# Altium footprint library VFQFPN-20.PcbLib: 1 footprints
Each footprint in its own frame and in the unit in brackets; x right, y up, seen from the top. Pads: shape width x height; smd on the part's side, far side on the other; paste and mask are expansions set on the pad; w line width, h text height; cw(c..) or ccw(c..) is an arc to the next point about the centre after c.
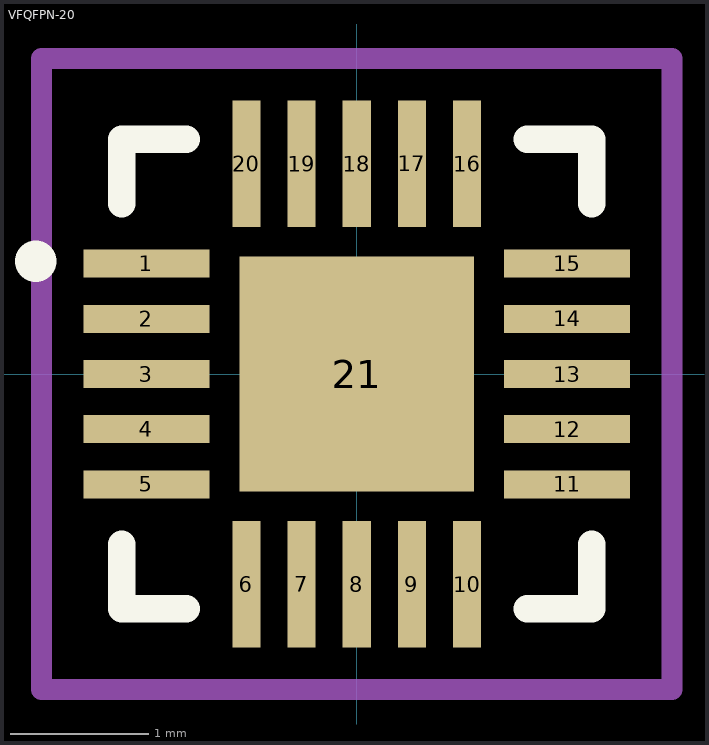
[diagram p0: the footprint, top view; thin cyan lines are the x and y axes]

## VFQFPN-20 [mil]
pads (21):
  rect 36x8 smd: 1(-60,31.5) 2(-60,15.75) 3(-60,0) 4(-60,-15.75) 5(-60,-31.5) 11(60,-31.5) 12(60,-15.75) 13(60,0) 14(60,15.75) 15(60,31.5)
  rect 8x36 smd: 6(-31.5,-60) 7(-15.75,-60) 8(0,-60) 9(15.75,-60) 10(31.5,-60) 16(31.5,60) 17(15.75,60) 18(0,60) 19(-15.75,60) 20(-31.5,60)
  rect 67x67 smd: 21(0,0)
Top Overlay:
  circle w11.81: c-91.57,32.15 r0
  lines w7.87: -67,-48.6 -67,-67 -48.6,-67 ; -67,48.6 -67,67 -48.6,67 ; 48.6,-67 67,-67 67,-48.6 ; 48.6,67 67,67 67,48.6
Mechanical 15:
  lines w6: -90,-90 -90,-55.5 -90,74 -90,90 -47.5,90 63.5,90 90,90 90,47.5 90,-90 82,-90 55.5,-90 -55.5,-90 -90,-90
3D body "VFQFPN20_3X3_STM.step": height 39.09, standoff 0, extent -62.01,-62.01 62.01,62.01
